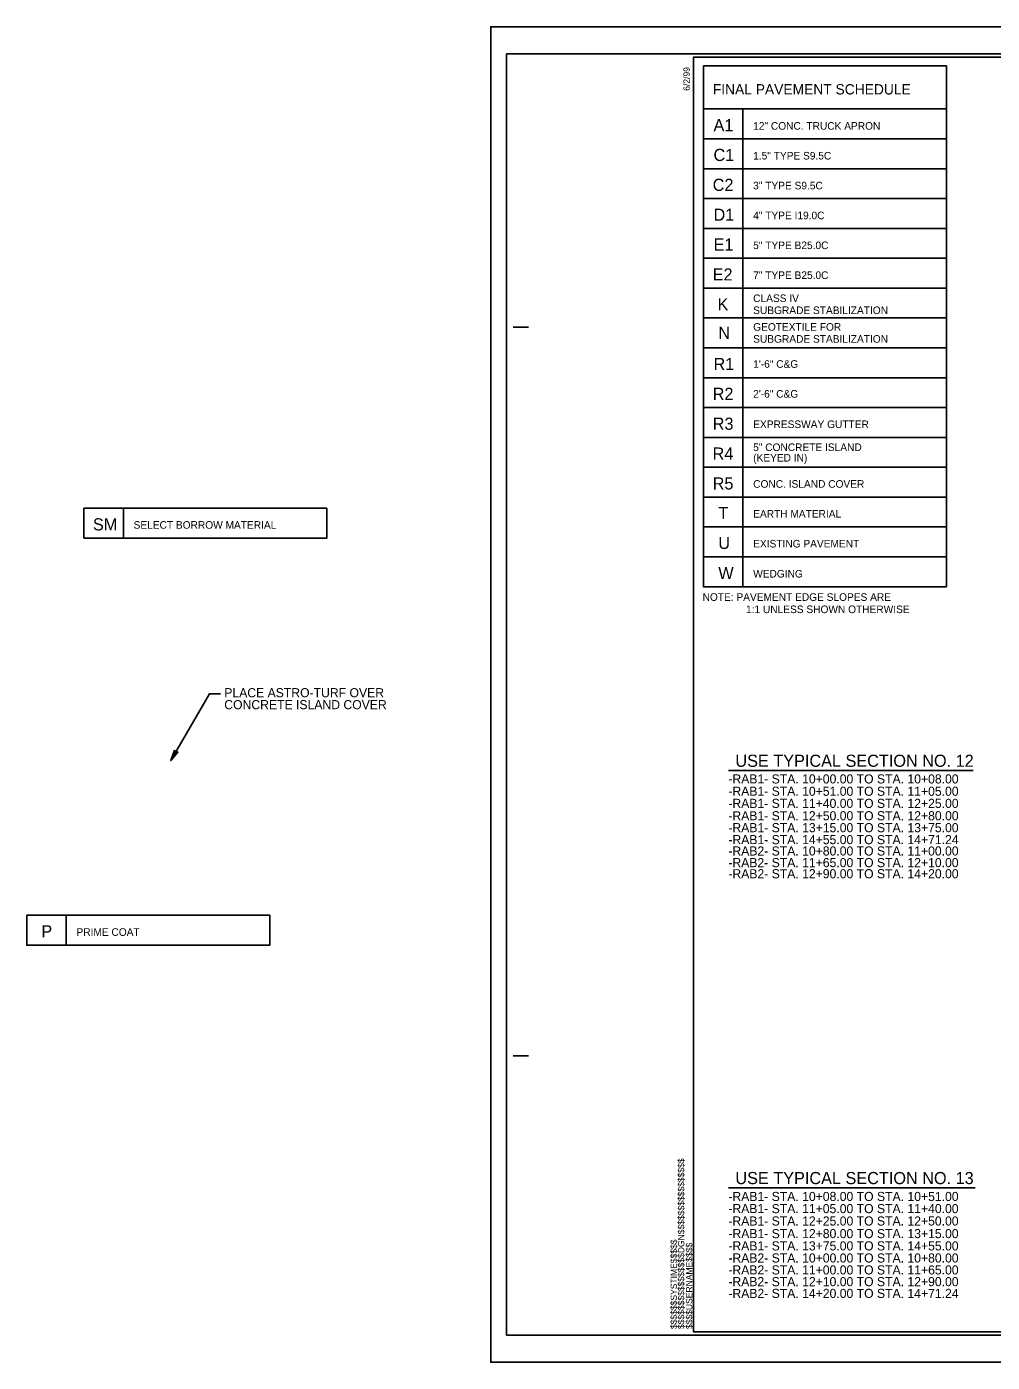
# Model space of a CAD drawing. Extents: x 573748 to 574632, y -54663 to -53209.
# Drawn here: x 573867.8 to 574026.7, y -54603.6 to -54383.6 of the extents above; entities that cross this region are included whole.
import ezdxf

# ---------------------------------------------------------------- set-up
doc = ezdxf.new("R2010")
doc.units = 0
for name, color, linetype in [('Prop Dimension', 7, 'Continuous'), ('Prop Dimension Text', 7, 'Continuous'), ('Prop Pavement Schedule Description CELL', 7, 'Continuous'), ('Prop Terminator CELL', 7, 'Continuous'), ('Sheet Cutting Line CELL', 7, 'Continuous'), ('Sheet Plot Border Inside CELL', 7, 'Continuous'), ('Sheet Plot Border Outside CELL', 7, 'Continuous'), ('Sheet Typical CELL', 7, 'Continuous'), ('Typical Text General CELL', 7, 'Continuous')]:
    doc.layers.add(name, color=color, linetype=linetype)

msp = doc.modelspace()

# ---------------------------------------------------------------- linework, layer by layer
at = {"layer": 'Prop Dimension'}
msp.add_lwpolyline([(573891.48, -54504.52), (573897.85, -54493.55), (573899.7, -54493.55)], dxfattribs=at)
at = {"layer": 'Prop Pavement Schedule Description CELL'}
msp.add_lwpolyline([(573979.19, -54390.11), (574019.2, -54390.11), (574019.2, -54397.2), (573979.19, -54397.2)], close=True, dxfattribs=at)
for points in [[(573985.7, -54402.11), (573979.19, -54402.11), (573979.19, -54397.2), (574019.2, -54397.2), (574019.2, -54402.11), (573985.7, -54402.11), (573985.7, -54397.2)], [(573985.7, -54407.03), (573979.19, -54407.03), (573979.19, -54402.11), (574019.2, -54402.11), (574019.2, -54407.03), (573985.7, -54407.03), (573985.7, -54402.11)], [(573985.7, -54411.95), (573979.19, -54411.95), (573979.19, -54407.03), (574019.2, -54407.03), (574019.2, -54411.95), (573985.7, -54411.95), (573985.7, -54407.03)], [(573985.7, -54416.87), (573979.19, -54416.87), (573979.19, -54411.95), (574019.2, -54411.95), (574019.2, -54416.87), (573985.7, -54416.87), (573985.7, -54411.95)], [(573985.7, -54421.79), (573979.19, -54421.79), (573979.19, -54416.87), (574019.2, -54416.87), (574019.2, -54421.79), (573985.7, -54421.79), (573985.7, -54416.87)], [(573985.7, -54426.71), (573979.19, -54426.71), (573979.19, -54421.79), (574019.2, -54421.79), (574019.2, -54426.71), (573985.7, -54426.71), (573985.7, -54421.79)], [(573985.7, -54431.62), (573979.19, -54431.62), (573979.19, -54426.71), (574019.2, -54426.71), (574019.2, -54431.62), (573985.7, -54431.62), (573985.7, -54426.71)], [(573985.7, -54436.54), (573979.19, -54436.54), (573979.19, -54431.62), (574019.2, -54431.62), (574019.2, -54436.54), (573985.7, -54436.54), (573985.7, -54431.62)], [(573985.7, -54441.46), (573979.19, -54441.46), (573979.19, -54436.54), (574019.2, -54436.54), (574019.2, -54441.46), (573985.7, -54441.46), (573985.7, -54436.54)], [(573985.7, -54446.38), (573979.19, -54446.38), (573979.19, -54441.46), (574019.2, -54441.46), (574019.2, -54446.38), (573985.7, -54446.38), (573985.7, -54441.46)], [(573985.7, -54451.3), (573979.19, -54451.3), (573979.19, -54446.38), (574019.2, -54446.38), (574019.2, -54451.3), (573985.7, -54451.3), (573985.7, -54446.38)], [(573985.7, -54456.22), (573979.19, -54456.22), (573979.19, -54451.3), (574019.2, -54451.3), (574019.2, -54456.22), (573985.7, -54456.22), (573985.7, -54451.3)], [(573985.7, -54461.13), (573979.19, -54461.13), (573979.19, -54456.22), (574019.2, -54456.22), (574019.2, -54461.13), (573985.7, -54461.13), (573985.7, -54456.22)], [(573883.69, -54467.88), (573877.18, -54467.88), (573877.18, -54462.96), (573917.18, -54462.96), (573917.18, -54467.88), (573883.69, -54467.88), (573883.69, -54462.96)], [(573985.7, -54466.05), (573979.19, -54466.05), (573979.19, -54461.13), (574019.2, -54461.13), (574019.2, -54466.05), (573985.7, -54466.05), (573985.7, -54461.13)], [(573985.7, -54470.97), (573979.19, -54470.97), (573979.19, -54466.05), (574019.2, -54466.05), (574019.2, -54470.97), (573985.7, -54470.97), (573985.7, -54466.05)], [(573985.7, -54475.89), (573979.19, -54475.89), (573979.19, -54470.97), (574019.2, -54470.97), (574019.2, -54475.89), (573985.7, -54475.89), (573985.7, -54470.97)], [(573874.29, -54534.94), (573867.77, -54534.94), (573867.77, -54530.02), (573907.78, -54530.02), (573907.78, -54534.94), (573874.29, -54534.94), (573874.29, -54530.02)]]:
    msp.add_lwpolyline(points, dxfattribs=at)
at = {"layer": 'Prop Terminator CELL'}
msp.add_lwpolyline([(573892.12, -54502.81), (573891.48, -54504.52), (573892.67, -54503.12), (573892.27, -54503.15)], close=True, dxfattribs=at)
at = {"layer": 'Sheet Cutting Line CELL'}
for p, q in [((574280.97, -54383.65), (573944.17, -54383.65)), ((573944.17, -54383.65), (573944.17, -54603.65)), ((573944.17, -54603.65), (574280.97, -54603.65))]:
    msp.add_line(p, q, dxfattribs=at)
at = {"layer": 'Sheet Plot Border Inside CELL'}
msp.add_lwpolyline([(574280.07, -54388.14), (573946.77, -54388.14), (573946.77, -54599.16), (574280.07, -54599.16)], close=True, dxfattribs=at)
at = {"layer": 'Sheet Plot Border Outside CELL'}
msp.add_lwpolyline([(574280.97, -54383.65), (573944.17, -54383.65), (573944.17, -54603.65), (574280.97, -54603.65)], close=True, dxfattribs=at)
at = {"layer": 'Sheet Typical CELL'}
for p, q in [((573947.87, -54433.15), (573950.37, -54433.15)), ((573947.87, -54553.15), (573950.37, -54553.15)), ((573977.57, -54598.65), (573977.57, -54598.65)), ((573977.57, -54598.65), (573977.57, -54598.65)), ((573977.57, -54598.65), (573977.57, -54598.65)), ((573977.57, -54598.65), (573977.57, -54598.65)), ((573977.57, -54598.65), (573977.57, -54598.65)), ((573977.57, -54598.65), (573977.57, -54598.65))]:
    msp.add_line(p, q, dxfattribs=at)
msp.add_lwpolyline([(574277.57, -54388.65), (573977.57, -54388.65), (573977.57, -54598.65), (574277.57, -54598.65)], close=True, dxfattribs=at)
msp.add_lwpolyline([(573985.07, -54598.65), (573985.07, -54598.65)], dxfattribs=at)
at = {"layer": 'Typical Text General CELL'}
for p, q in [((573983.3, -54506.16), (574023.58, -54506.16)), ((573983.3, -54574.91), (574023.91, -54574.91))]:
    msp.add_line(p, q, dxfattribs=at)

# ---------------------------------------------------------------- texts
at = {"layer": 'Prop Dimension Text'}
for s, p in [('PLACE ASTRO-TURF OVER', (573900.3, -54494.1)), ('CONCRETE ISLAND COVER', (573900.3, -54496.07))]:
    msp.add_text(s, height=1.5, dxfattribs=at).set_placement(p)
at = {"layer": 'Prop Pavement Schedule Description CELL'}
for s, height, p in [('FINAL PAVEMENT SCHEDULE', 1.7, (573980.73, -54394.81)), ('A1', 2, (573980.85, -54400.86)), ('12" CONC. TRUCK APRON', 1.25, (573987.38, -54400.61)), ('C1', 2, (573980.85, -54405.77)), ('1.5" TYPE S9.5C', 1.25, (573987.38, -54405.52)), ('C2', 2, (573980.71, -54410.69)), ('3" TYPE S9.5C', 1.25, (573987.38, -54410.44)), ('D1', 2, (573980.85, -54415.61)), ('4" TYPE I19.0C', 1.25, (573987.38, -54415.36)), ('E1', 2, (573980.85, -54420.53)), ('5" TYPE B25.0C', 1.25, (573987.38, -54420.28)), ('E2', 2, (573980.71, -54425.45)), ('7" TYPE B25.0C', 1.25, (573987.38, -54425.2)), ('CLASS IV', 1.25, (573987.38, -54429)), ('K', 2, (573981.51, -54430.37)), ('SUBGRADE STABILIZATION', 1.25, (573987.38, -54430.98)), ('N', 2, (573981.64, -54435.08)), ('SUBGRADE STABILIZATION', 1.25, (573987.38, -54435.7)), ('GEOTEXTILE FOR', 1.25, (573987.38, -54433.72)), ('R1', 2, (573980.85, -54440.2)), ('1\'-6" C&G', 1.25, (573987.38, -54439.83)), ('R2', 2, (573980.71, -54445.12)), ('2\'-6" C&G', 1.25, (573987.38, -54444.75)), ('R3', 2, (573980.72, -54450.04)), ('EXPRESSWAY GUTTER', 1.25, (573987.38, -54449.76)), ('R4', 2, (573980.7, -54454.96)), ('5" CONCRETE ISLAND', 1.25, (573987.38, -54453.54)), ('(KEYED IN)', 1.25, (573987.38, -54455.28)), ('R5', 2, (573980.71, -54459.88)), ('CONC. ISLAND COVER', 1.25, (573987.38, -54459.59)), ('T', 2, (573981.64, -54464.76)), ('SM', 2, (573878.68, -54466.62)), ('SELECT BORROW MATERIAL', 1.25, (573885.37, -54466.34)), ('EARTH MATERIAL', 1.25, (573987.38, -54464.51)), ('U', 2, (573981.64, -54469.68)), ('EXISTING PAVEMENT', 1.25, (573987.38, -54469.43)), ('W', 2, (573981.64, -54474.63)), ('WEDGING', 1.25, (573987.38, -54474.38)), ('NOTE: PAVEMENT EDGE SLOPES ARE', 1.25, (573979.05, -54478.22)), ('1:1 UNLESS SHOWN OTHERWISE', 1.25, (573986.2, -54480.24)), ('P', 2, (573870.18, -54533.65)), ('PRIME COAT', 1.25, (573875.97, -54533.4))]:
    msp.add_text(s, height=height, dxfattribs=at).set_placement(p)
at = {"layer": 'Sheet Typical CELL'}
for s, p in [('6/2/99', (573976.94, -54394.2)), ('$$$$$$$$$$$$$$$$DGN$$$$$$$$$$$$$$$$', (573976.04, -54598.17)), ('$$$$$$SYSTIME$$$$$', (573974.83, -54598.17)), ('$$$$USERNAME$$$$', (573977.36, -54598.17))]:
    msp.add_text(s, height=1.05, rotation=90, dxfattribs=at).set_placement(p)
at = {"layer": 'Typical Text General CELL'}
for s, height, p in [('USE TYPICAL SECTION NO. 12', 2, (573984.45, -54505.56)), ('-RAB1- STA. 10+00.00 TO STA. 10+08.00', 1.5, (573983.29, -54508.3)), ('-RAB1- STA. 10+51.00 TO STA. 11+05.00', 1.5, (573983.29, -54510.33)), ('-RAB1- STA. 11+40.00 TO STA. 12+25.00', 1.5, (573983.29, -54512.33)), ('-RAB1- STA. 12+50.00 TO STA. 12+80.00', 1.5, (573983.29, -54514.37)), ('-RAB1- STA. 13+15.00 TO STA. 13+75.00', 1.5, (573983.29, -54516.33)), ('-RAB1- STA. 14+55.00 TO STA. 14+71.24', 1.5, (573983.29, -54518.3)), ('-RAB2- STA. 10+80.00 TO STA. 11+00.00', 1.5, (573983.29, -54520.17)), ('-RAB2- STA. 11+65.00 TO STA. 12+10.00', 1.5, (573983.29, -54522.09)), ('-RAB2- STA. 12+90.00 TO STA. 14+20.00', 1.5, (573983.29, -54523.92)), ('USE TYPICAL SECTION NO. 13', 2, (573984.45, -54574.3)), ('-RAB1- STA. 10+08.00 TO STA. 10+51.00', 1.5, (573983.29, -54577.08)), ('-RAB1- STA. 11+05.00 TO STA. 11+40.00', 1.5, (573983.29, -54579.08)), ('-RAB1- STA. 12+25.00 TO STA. 12+50.00', 1.5, (573983.29, -54581.12)), ('-RAB1- STA. 12+80.00 TO STA. 13+15.00', 1.5, (573983.29, -54583.2)), ('-RAB1- STA. 13+75.00 TO STA. 14+55.00', 1.5, (573983.29, -54585.22)), ('-RAB2- STA. 10+00.00 TO STA. 10+80.00', 1.5, (573983.29, -54587.21)), ('-RAB2- STA. 11+00.00 TO STA. 11+65.00', 1.5, (573983.29, -54589.18)), ('-RAB2- STA. 12+10.00 TO STA. 12+90.00', 1.5, (573983.29, -54591.11)), ('-RAB2- STA. 14+20.00 TO STA. 14+71.24', 1.5, (573983.29, -54593.05))]:
    msp.add_text(s, height=height, dxfattribs=at).set_placement(p)

doc.saveas('drawing.dxf')
